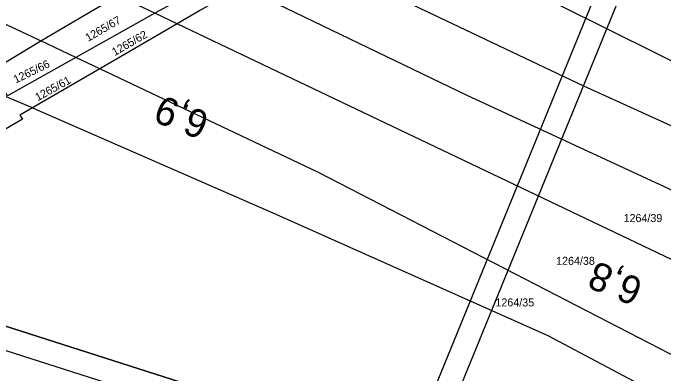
# Model space of a CAD drawing. Extents: x -779302 to -774398, y -1144902 to -1142831.
# Drawn here: x -777063.2 to -776925.1, y -1143987.9 to -1143911.3 of the extents above; entities that cross this region are included whole.
import ezdxf

# ---------------------------------------------------------------- set-up
doc = ezdxf.new("R2010")
doc.units = 0
for name, color, linetype in [('Hranice parcel', 7, 'Continuous'), ('Parcelní čísla', 7, 'Continuous'), ('Vrstva 1', 7, 'Continuous'), ('zjednodus_g_situ-seda - Vrstva 7', 7, 'Continuous')]:
    doc.layers.add(name, color=color, linetype=linetype)

msp = doc.modelspace()

# ---------------------------------------------------------------- linework, layer by layer
at = {"layer": 'Hranice parcel'}
for p, q in [((-777033.09, -1143911.38), (-777041.02, -1143907.6)), ((-777028.37, -1143913.63), (-777033.09, -1143911.38)), ((-777049.85, -1143920.77), (-777057.27, -1143917.26)), ((-777049.85, -1143920.77), (-777064.35, -1143928.9)), ((-777044.79, -1143923.17), (-777049.85, -1143920.77)), ((-777044.79, -1143923.17), (-777059.08, -1143931.47)), ((-777059.08, -1143931.47), (-777064.63, -1143929.09))]:
    msp.add_line(p, q, dxfattribs=at)
for points in [[(-777126.53, -1143884.78), (-777059.22, -1143916.33), (-777057.27, -1143917.26)], [(-776817.86, -1143983.94), (-776814.26, -1143974.07), (-776869.06, -1143948.13), (-776905.56, -1143930.42), (-776989.05, -1143888.84)], [(-776819.3, -1143987.88), (-776871.91, -1143959.94), (-776915.87, -1143938.7), (-776942.03, -1143926.84), (-776978.29, -1143909.65), (-777001.23, -1143897.87)], [(-777019.12, -1143903.55), (-777028.04, -1143908.55), (-777033.09, -1143911.38)], [(-777014.7, -1143905.69), (-777023.42, -1143910.75), (-777028.37, -1143913.63)], [(-776828.14, -1143996.73), (-776887.84, -1143965.39), (-776966.84, -1143928.84), (-777014.7, -1143905.69)], [(-777057.27, -1143917.26), (-777050.08, -1143912.98), (-777041.02, -1143907.6)], [(-777033.09, -1143911.38), (-777042.34, -1143916.56), (-777049.85, -1143920.77)], [(-777028.37, -1143913.63), (-777037.37, -1143918.86), (-777044.79, -1143923.17)], [(-776843.21, -1144004.32), (-776917.2, -1143966.59), (-777028.37, -1143913.63)], [(-777064.35, -1143928.9), (-777067.77, -1143923.5), (-777057.27, -1143917.26)], [(-776864.86, -1144013.82), (-776884.37, -1144004.05), (-776998.38, -1143945.16), (-777044.79, -1143923.17)], [(-777059.08, -1143931.47), (-777061.75, -1143933.02), (-777061.19, -1143933.89), (-777087.76, -1143949.47)], [(-777059.08, -1143931.47), (-777007.46, -1143954.02), (-776949.67, -1143979.74), (-776875.92, -1144018.96)]]:
    msp.add_lwpolyline(points, dxfattribs=at)
at = {"layer": 'Vrstva 1'}
for points in [[(-776700.65, -1144099.52), (-777891.15, -1143718.47), (-777803.66, -1143445.14), (-776613.17, -1143826.19)], [(-776619.45, -1143829.42), (-777605.19, -1143513.91), (-777689.63, -1143777.73), (-776703.89, -1144093.24)], [(-776703.89, -1144093.24), (-777689.63, -1143777.73), (-777605.19, -1143513.91), (-776619.45, -1143829.42)], [(-775713.68, -1144238.31), (-776879.99, -1143761.57), (-776992.36, -1144036.48), (-775826.05, -1144513.22)], [(-775828.78, -1144506.7), (-776985.84, -1144033.74), (-776877.25, -1143768.09), (-775720.2, -1144241.05)]]:
    msp.add_lwpolyline(points, close=True, dxfattribs=at)

# ---------------------------------------------------------------- texts
at = {"layer": 'Parcelní čísla'}
for s, rotation, p in [('1265/67', 30, (-777047.26, -1143917.46)), ('1265/62', 30, (-777041.62, -1143920.49)), ('1265/66', 26, (-777062.61, -1143926.31)), ('1265/61', 29, (-777057.94, -1143930.08))]:
    msp.add_text(s, height=1.7, rotation=rotation, dxfattribs=at).set_placement(p)
for s, p in [('1264/39', (-776933.63, -1143955.69)), ('1264/38', (-776947.95, -1143964.76)), ('1264/35', (-776960.83, -1143973.59))]:
    msp.add_text(s, height=1.7, dxfattribs=at).set_placement(p)
at = {"layer": 'zjednodus_g_situ-seda - Vrstva 7'}
for s, rotation, p in [('6,9', 158.4292, (-777021.17, -1143932.74)), ('6,8', 157.7004, (-776929.13, -1143968.06))]:
    msp.add_text(s, height=6, rotation=rotation, dxfattribs=at).set_placement(p)

doc.saveas('drawing.dxf')
